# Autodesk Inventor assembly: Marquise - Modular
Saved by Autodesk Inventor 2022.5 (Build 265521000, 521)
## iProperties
Created: 2025-01
Part Number: Marquise - Modular
Document SubType Name: Assembly
Designer: AdminForWorker
Title: Marquise - Modular v10
Author: AdminForWorker
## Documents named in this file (4)
- c:\worker\convert-fusion-r06-cosv3\tmp\job-1\42\temp\files\ebf93e40-a6ef-46be-a88c-efc3c2b7e559\489f5455-fe5d-44a8-9691-2d16e9a02546.iam
- c:\worker\convert-fusion-r06-cosv3\tmp\job-1\42\temp\files\ebf93e40-a6ef-46be-a88c-efc3c2b7e559\Modular - Placebo - Bayonet Connector v4.ipt
- c:\worker\convert-fusion-r06-cosv3\tmp\job-1\42\temp\files\ebf93e40-a6ef-46be-a88c-efc3c2b7e559\Marquise Modular.ipt
- c:\worker\convert-fusion-r06-cosv3\tmp\job-1\42\temp\files\ebf93e40-a6ef-46be-a88c-efc3c2b7e559\Modular - Placedo - Cord Set v4.ipt
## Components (3 placed, 3 different names)
1. Modular - Placebo - Bayonet Connector v4:1
2. Marquise Modular:1
3. Modular - Placedo - Cord Set v4:1
